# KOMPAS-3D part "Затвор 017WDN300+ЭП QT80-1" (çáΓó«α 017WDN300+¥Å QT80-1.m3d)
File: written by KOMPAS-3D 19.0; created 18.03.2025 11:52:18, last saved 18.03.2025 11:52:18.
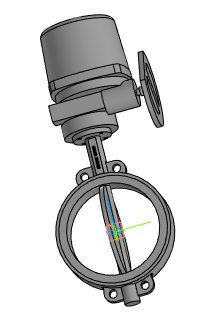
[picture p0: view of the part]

Document properties: Полное имя файла: Затвор 017WDN300+ЭП QT80-1.a3d

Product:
- Part/product: Затвор 017WDN300+ЭП QT80-1
    Масса: 160.023

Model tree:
1. Операция без истории:1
